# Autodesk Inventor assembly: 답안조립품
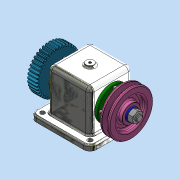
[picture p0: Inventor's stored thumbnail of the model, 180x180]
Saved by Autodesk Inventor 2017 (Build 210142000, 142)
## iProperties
Part Number: 답안조립품
Material: 일반
Document SubType Name: Assembly
Designer: MRC
Author: MRC
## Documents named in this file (12)
- C:\Users\MRC\Desktop\720706V1020\답안조립품.iam
- C:\Users\MRC\Desktop\720706V1020\V벨트풀리.ipt
- C:\Users\MRC\Desktop\720706V1020\너트 M12x1.25.ipt
- C:\Users\MRC\Desktop\720706V1020\베어링 6204.ipt
- C:\Users\MRC\Desktop\720706V1020\본체.ipt
- C:\Users\MRC\Desktop\720706V1020\볼트 M4x0.7.ipt
- C:\Users\MRC\Desktop\720706V1020\스퍼기어.ipt
- C:\Users\MRC\Desktop\720706V1020\오일실 20x35x8.ipt
- C:\Users\MRC\Desktop\720706V1020\와셔 12x24.ipt
- C:\Users\MRC\Desktop\720706V1020\축.ipt
- C:\Users\MRC\Desktop\720706V1020\커버.ipt
- C:\Users\MRC\Desktop\720706V1020\키 5x5.ipt
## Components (1 placed, 1 different names)
1. V벨트풀리:3
